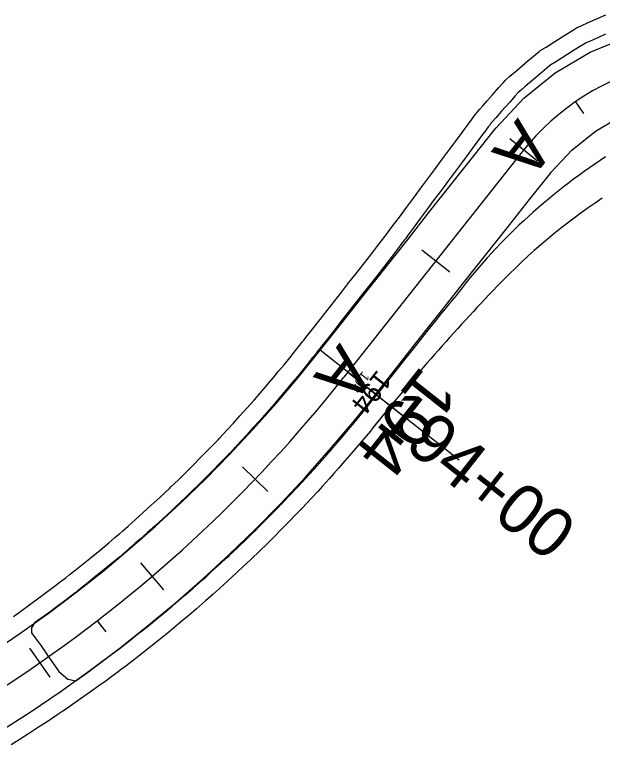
# Model space of a CAD drawing. Extents: x 1823824 to 1861612, y 706975 to 726130.
# Drawn here: x 1825898.7 to 1825981.6, y 712800.3 to 712904.6 of the extents above; entities that cross this region are included whole.
import ezdxf

# ---------------------------------------------------------------- set-up
doc = ezdxf.new("R2010")
doc.units = 0
for name, color, linetype in [('DR_X_Flood_Boundary', 7, 'Continuous'), ('GE_X_CL_10', 7, 'Continuous'), ('GE_X_CL_100', 7, 'Continuous'), ('GE_X_CL_20', 7, 'Continuous'), ('GE_X_CL_200', 7, 'Continuous'), ('GE_X_CL_50', 7, 'Continuous'), ('SC_Scratch2', 7, 'Continuous'), ('SC_Scratch5', 7, 'Continuous'), ('SC_Scratch6', 7, 'Continuous')]:
    doc.layers.add(name, color=color, linetype=linetype)

msp = doc.modelspace()

# ---------------------------------------------------------------- linework, layer by layer
at = {"layer": 'DR_X_Flood_Boundary'}
msp.add_line((1825970.3, 712885.19), (1825945.16, 712853.4), dxfattribs=at)
for centre, radius, start, end in [((1825997.75, 712863.48), 35, 65.2301, 141.6626), ((1825788.29, 712977.46), 200, 285.7144, 321.6626)]:
    msp.add_arc(centre, radius, start, end, dxfattribs=at)
at = {"layer": 'GE_X_CL_10'}
for p, q in [((1825977.85, 712892.27), (1825978.42, 712891.44)), ((1825945.73, 712854.12), (1825946.51, 712853.49)), ((1825910.32, 712819), (1825910.93, 712818.21))]:
    msp.add_line(p, q, dxfattribs=at)
at = {"layer": 'GE_X_CL_100'}
msp.add_line((1825945.73, 712854.12), (1825953.57, 712847.91), dxfattribs=at)
at = {"layer": 'GE_X_CL_20'}
for p, q in [((1825977.85, 712892.27), (1825978.99, 712890.62)), ((1825945.73, 712854.12), (1825947.3, 712852.87)), ((1825910.32, 712819), (1825911.54, 712817.42))]:
    msp.add_line(p, q, dxfattribs=at)
at = {"layer": 'GE_X_CL_200'}
msp.add_line((1825945.73, 712854.12), (1825961.42, 712841.71), dxfattribs=at)
at = {"layer": 'GE_X_CL_50'}
msp.add_line((1825945.73, 712854.12), (1825949.65, 712851.01), dxfattribs=at)
at = {"layer": 'SC_Scratch2'}
for p, q in [((1825980.69, 712888.15), (1825984.38, 712890.33)), ((1825977.35, 712885.47), (1825980.69, 712888.15)), ((1825974.43, 712882.34), (1825977.35, 712885.47)), ((1825974.22, 712882.08), (1825974.43, 712882.34)), ((1825971.36, 712878.47), (1825974.22, 712882.08)), ((1825968.26, 712874.54), (1825971.36, 712878.47)), ((1825965.16, 712870.62), (1825968.26, 712874.54)), ((1825962.06, 712866.7), (1825965.16, 712870.62)), ((1825958.96, 712862.78), (1825962.06, 712866.7)), ((1825955.85, 712858.86), (1825958.96, 712862.78)), ((1825952.75, 712854.94), (1825955.85, 712858.86)), ((1825949.65, 712851.01), (1825952.75, 712854.94)), ((1825949.09, 712850.3), (1825949.65, 712851.01)), ((1825946.45, 712847.04), (1825949.09, 712850.3)), ((1825943.14, 712843.13), (1825946.45, 712847.04)), ((1825939.74, 712839.3), (1825943.14, 712843.13)), ((1825936.24, 712835.55), (1825939.74, 712839.3)), ((1825932.64, 712831.9), (1825936.24, 712835.55)), ((1825928.96, 712828.34), (1825932.64, 712831.9)), ((1825925.19, 712824.87), (1825928.96, 712828.34)), ((1825921.33, 712821.49), (1825925.19, 712824.87)), ((1825917.39, 712818.22), (1825921.33, 712821.49)), ((1825913.37, 712815.04), (1825917.39, 712818.22)), ((1825909.27, 712811.96), (1825913.37, 712815.04)), ((1825905.09, 712808.99), (1825909.27, 712811.96)), ((1825900.85, 712806.12), (1825905.09, 712808.99)), ((1825896.53, 712803.36), (1825900.85, 712806.12))]:
    msp.add_line(p, q, dxfattribs=at)
for points in [[(1825929.56, 712846.92), (1825930.47, 712847.92), (1825931.46, 712849.02), (1825932.52, 712850.22), (1825933.32, 712851.14), (1825933.87, 712851.77), (1825934.17, 712852.12), (1825934.61, 712852.64), (1825935.2, 712853.35), (1825935.94, 712854.23), (1825936.7, 712855.15), (1825937.5, 712856.13), (1825938.32, 712857.16), (1825938.93, 712857.92), (1825939.33, 712858.42), (1825939.51, 712858.65), (1825939.98, 712859.25), (1825940.72, 712860.2), (1825941.75, 712861.51), (1825942.78, 712862.82), (1825943.81, 712864.13), (1825944.84, 712865.44), (1825945.87, 712866.75), (1825946.9, 712868.06), (1825947.93, 712869.37), (1825948.95, 712870.69), (1825949.97, 712872.01), (1825950.98, 712873.33), (1825951.99, 712874.66), (1825952.99, 712876), (1825953.98, 712877.34), (1825954.97, 712878.68), (1825955.96, 712880.02), (1825956.96, 712881.36), (1825957.95, 712882.7), (1825958.94, 712884.04), (1825959.93, 712885.38), (1825960.9, 712886.68), (1825961.84, 712887.96), (1825962.76, 712889.19), (1825963.4, 712890.06), (1825963.76, 712890.55), (1825963.86, 712890.67), (1825964.05, 712890.91), (1825964.35, 712891.25), (1825964.76, 712891.71), (1825965.33, 712892.37), (1825966.08, 712893.21), (1825966.99, 712894.24), (1825967.63, 712894.96), (1825967.98, 712895.35), (1825968.06, 712895.43), (1825968.61, 712895.9), (1825969.64, 712896.77), (1825971.14, 712898.05), (1825972.17, 712898.92), (1825972.73, 712899.39), (1825972.82, 712899.46), (1825972.91, 712899.52), (1825973.01, 712899.59), (1825973.11, 712899.65), (1825973.7, 712900.02), (1825974.78, 712900.7), (1825976.35, 712901.69), (1825977.43, 712902.36), (1825978.02, 712902.73), (1825978.12, 712902.78), (1825978.66, 712903.03), (1825979.64, 712903.47), (1825981.06, 712904.1), (1825982.14, 712904.58)], [(1825895.36, 712814.48), (1825899.4, 712817.21), (1825903.37, 712820.04), (1825907.27, 712822.96), (1825911.09, 712825.98), (1825914.84, 712829.1), (1825918.51, 712832.31), (1825922.1, 712835.61), (1825925.6, 712839), (1825929.02, 712842.48), (1825932.35, 712846.04), (1825935.59, 712849.68), (1825938.74, 712853.4), (1825941.24, 712856.5), (1825941.81, 712857.22), (1825944.91, 712861.14), (1825948.01, 712865.06), (1825951.11, 712868.98), (1825954.21, 712872.9), (1825957.31, 712876.83), (1825960.42, 712880.75), (1825963.52, 712884.67), (1825966.38, 712888.29), (1825966.66, 712888.63), (1825970.55, 712892.8), (1825975.01, 712896.38), (1825979.92, 712899.28), (1825985.2, 712901.46)], [(1825982.1, 712901.83), (1825981.1, 712901.38), (1825980.34, 712901.04), (1825979.82, 712900.81), (1825979.46, 712900.65), (1825979.26, 712900.56), (1825979.23, 712900.54), (1825978.67, 712900.19), (1825977.59, 712899.52), (1825976, 712898.51), (1825974.92, 712897.84), (1825974.36, 712897.49), (1825974.33, 712897.46), (1825974.3, 712897.44), (1825974.27, 712897.42), (1825974.24, 712897.4), (1825973.88, 712897.1), (1825973.2, 712896.53), (1825972.2, 712895.68), (1825971.38, 712894.98), (1825970.73, 712894.43), (1825970.27, 712894.03), (1825969.95, 712893.76), (1825969.78, 712893.62), (1825969.76, 712893.59), (1825969.35, 712893.14), (1825968.57, 712892.25), (1825967.41, 712890.94), (1825966.59, 712890.01), (1825966.13, 712889.49), (1825966.02, 712889.36), (1825965.93, 712889.27), (1825965.88, 712889.2), (1825965.85, 712889.17), (1825965.81, 712889.11), (1825965.76, 712889.05), (1825965.7, 712888.96), (1825965.57, 712888.79), (1825965.38, 712888.54), (1825965.13, 712888.2), (1825964.74, 712887.67), (1825964.21, 712886.96), (1825963.55, 712886.06), (1825962.78, 712885.02), (1825961.89, 712883.83), (1825960.9, 712882.49), (1825959.91, 712881.15), (1825958.92, 712879.81), (1825957.92, 712878.47), (1825956.93, 712877.13), (1825955.94, 712875.79), (1825954.95, 712874.45), (1825954.25, 712873.5), (1825953.84, 712872.95), (1825953.72, 712872.8), (1825953.34, 712872.31), (1825952.71, 712871.47), (1825951.81, 712870.3), (1825950.88, 712869.09), (1825949.89, 712867.82), (1825948.86, 712866.51)], [(1825948.86, 712866.51), (1825947.83, 712865.2), (1825946.8, 712863.89), (1825945.77, 712862.58), (1825944.74, 712861.27), (1825943.71, 712859.96), (1825942.69, 712858.65), (1825942, 712857.77), (1825941.64, 712857.32), (1825941.63, 712857.3), (1825941.56, 712857.22), (1825941.44, 712857.06), (1825941.27, 712856.84), (1825941.13, 712856.67), (1825941.04, 712856.55), (1825940.98, 712856.48), (1825940.68, 712856.11), (1825940.15, 712855.44), (1825939.38, 712854.48), (1825938.63, 712853.56), (1825937.9, 712852.68), (1825937.2, 712851.85), (1825936.72, 712851.27), (1825936.46, 712850.96), (1825936.41, 712850.91), (1825936.38, 712850.86), (1825936.35, 712850.83), (1825936.33, 712850.81), (1825936.22, 712850.68), (1825936.03, 712850.45), (1825935.75, 712850.12), (1825935.54, 712849.87), (1825935.4, 712849.71), (1825935.34, 712849.64), (1825934.96, 712849.21), (1825934.27, 712848.42), (1825933.26, 712847.28), (1825932.31, 712846.23), (1825931.44, 712845.27), (1825930.64, 712844.4), (1825930.09, 712843.81), (1825929.79, 712843.49), (1825929.75, 712843.45), (1825929.72, 712843.41), (1825929.69, 712843.39), (1825929.68, 712843.38), (1825929.59, 712843.28), (1825929.42, 712843.1), (1825929.17, 712842.83), (1825928.99, 712842.63), (1825928.87, 712842.51), (1825928.82, 712842.45), (1825928.42, 712842.05), (1825927.68, 712841.29), (1825926.6, 712840.18), (1825925.58, 712839.15), (1825924.61, 712838.19), (1825923.69, 712837.3), (1825923.07, 712836.69), (1825922.74, 712836.37), (1825922.71, 712836.34), (1825922.68, 712836.31), (1825922.67, 712836.3), (1825922.66, 712836.29), (1825922.58, 712836.22), (1825922.44, 712836.08), (1825922.24, 712835.88), (1825922.09, 712835.73), (1825921.99, 712835.64), (1825921.95, 712835.6), (1825921.53, 712835.22), (1825920.75, 712834.5), (1825919.61, 712833.43), (1825918.5, 712832.42), (1825917.43, 712831.46), (1825916.4, 712830.55), (1825915.7, 712829.94), (1825915.33, 712829.62), (1825915.3, 712829.59), (1825915.23, 712829.53), (1825915.12, 712829.43), (1825914.96, 712829.29), (1825914.84, 712829.19), (1825914.77, 712829.12), (1825914.74, 712829.1), (1825914.31, 712828.74), (1825913.49, 712828.05), (1825912.28, 712827.04), (1825911.08, 712826.05), (1825909.91, 712825.1), (1825908.75, 712824.18), (1825907.98, 712823.56), (1825907.59, 712823.25), (1825907.57, 712823.24), (1825907.53, 712823.2), (1825907.46, 712823.15), (1825907.35, 712823.06), (1825907.28, 712823.01), (1825907.24, 712822.97), (1825907.22, 712822.96), (1825906.79, 712822.63)], [(1825909.26, 712811.94), (1825909.27, 712811.95), (1825909.73, 712812.29), (1825910.64, 712812.97), (1825912, 712813.99), (1825912.91, 712814.67), (1825913.37, 712815.01), (1825913.38, 712815.01), (1825913.82, 712815.36), (1825914.71, 712816.05), (1825916.03, 712817.09), (1825916.91, 712817.79), (1825917.37, 712818.14), (1825917.39, 712818.16), (1825917.84, 712818.53), (1825918.72, 712819.26), (1825920.02, 712820.33), (1825920.9, 712821.05), (1825921.34, 712821.42), (1825921.36, 712821.43), (1825921.78, 712821.8), (1825922.62, 712822.53), (1825923.87, 712823.62), (1825924.72, 712824.36), (1825925.16, 712824.74), (1825925.2, 712824.78), (1825925.64, 712825.18), (1825926.48, 712825.94), (1825927.71, 712827.07), (1825928.55, 712827.83), (1825928.98, 712828.22), (1825929, 712828.25), (1825929.41, 712828.64), (1825930.2, 712829.4), (1825931.38, 712830.54), (1825932.19, 712831.31), (1825932.62, 712831.72), (1825932.67, 712831.77), (1825933.09, 712832.2), (1825933.89, 712833), (1825935.06, 712834.18), (1825935.85, 712834.98), (1825936.26, 712835.4), (1825936.29, 712835.43), (1825936.69, 712835.85), (1825937.44, 712836.64), (1825938.54, 712837.82), (1825939.3, 712838.63), (1825939.72, 712839.07), (1825939.78, 712839.13), (1825940.19, 712839.59), (1825940.94, 712840.43), (1825942.04, 712841.65), (1825942.78, 712842.48), (1825943.18, 712842.93), (1825943.22, 712842.97), (1825943.6, 712843.41), (1825944.3, 712844.24), (1825945.33, 712845.45), (1825946.05, 712846.29), (1825946.44, 712846.76), (1825946.52, 712846.84), (1825946.85, 712847.25), (1825947.43, 712847.97), (1825948.28, 712849.01), (1825948.85, 712849.71), (1825949.16, 712850.09), (1825949.2, 712850.14), (1825949.29, 712850.25), (1825949.42, 712850.42), (1825949.61, 712850.66), (1825950.09, 712851.25), (1825950.84, 712852.2), (1825951.88, 712853.5), (1825952.92, 712854.81), (1825953.96, 712856.11), (1825954.99, 712857.41), (1825956.03, 712858.72), (1825957.07, 712860.02), (1825958.11, 712861.33), (1825958.91, 712862.33), (1825959.48, 712863.04), (1825959.82, 712863.46), (1825960.29, 712864.02), (1825960.73, 712864.56)], [(1825950.97, 712848.36), (1825950.67, 712847.98), (1825950.14, 712847.33), (1825949.67, 712846.75), (1825949.25, 712846.24), (1825948.89, 712845.8), (1825948.28, 712845.07)], [(1825898.48, 712819.62), (1825899.34, 712820.24), (1825900.61, 712821.15), (1825901.89, 712822.08), (1825903.17, 712823.03), (1825904.45, 712824), (1825905.33, 712824.67), (1825905.82, 712825.04), (1825905.92, 712825.12), (1825906.37, 712825.47), (1825907.17, 712826.11), (1825908.33, 712827.04), (1825909.51, 712828), (1825910.72, 712828.99), (1825911.95, 712830.02), (1825912.82, 712830.75), (1825913.33, 712831.19), (1825913.49, 712831.32), (1825913.94, 712831.72), (1825914.69, 712832.38), (1825915.74, 712833.3), (1825916.83, 712834.28), (1825917.96, 712835.32), (1825919.14, 712836.41), (1825919.99, 712837.2), (1825920.52, 712837.7), (1825920.73, 712837.9), (1825921.18, 712838.34), (1825921.88, 712839.02), (1825922.82, 712839.94), (1825923.82, 712840.93), (1825924.88, 712842), (1825926, 712843.15), (1825926.83, 712844), (1825927.38, 712844.57), (1825927.63, 712844.84), (1825928.08, 712845.32), (1825928.72, 712846.01), (1825929.56, 712846.92)], [(1825948.28, 712845.07), (1825947.41, 712844.04), (1825946.29, 712842.72), (1825945.31, 712841.58), (1825944.46, 712840.6), (1825943.74, 712839.8), (1825943.11, 712839.1), (1825942.58, 712838.51), (1825942.15, 712838.03), (1825941.46, 712837.28), (1825940.53, 712836.28), (1825939.34, 712835.02), (1825938.32, 712833.94), (1825937.45, 712833.05), (1825936.76, 712832.34), (1825936.12, 712831.7), (1825935.54, 712831.11), (1825935.02, 712830.59), (1825934.26, 712829.84), (1825933.26, 712828.87), (1825932.01, 712827.67), (1825930.95, 712826.67), (1825930.09, 712825.86), (1825929.42, 712825.24), (1825928.77, 712824.65), (1825928.14, 712824.07), (1825927.54, 712823.52), (1825926.7, 712822.78), (1825925.63, 712821.83), (1825924.32, 712820.7), (1825923.24, 712819.77), (1825922.38, 712819.04), (1825921.74, 712818.51), (1825921.08, 712817.97), (1825920.41, 712817.41), (1825919.71, 712816.83), (1825918.8, 712816.09), (1825917.66, 712815.19), (1825916.3, 712814.12), (1825915.19, 712813.26), (1825914.34, 712812.61), (1825913.74, 712812.16), (1825913.08, 712811.67), (1825912.36, 712811.13), (1825911.57, 712810.54), (1825910.57, 712809.82), (1825909.37, 712808.95), (1825907.95, 712807.96), (1825906.83, 712807.17), (1825905.99, 712806.59), (1825905.44, 712806.22), (1825904.78, 712805.78), (1825904.01, 712805.26), (1825903.12, 712804.66), (1825902.04, 712803.96), (1825900.77, 712803.14), (1825899.31, 712802.21), (1825898.18, 712801.5)], [(1825906.79, 712822.63), (1825905.93, 712821.98), (1825904.64, 712821.01), (1825903.47, 712820.14), (1825902.42, 712819.37), (1825901.47, 712818.69), (1825901.02, 712818.01), (1825901.05, 712817.31), (1825901.57, 712816.6), (1825902.38, 712815.45), (1825903.49, 712813.87), (1825904.89, 712811.86), (1825906.15, 712810.74), (1825907.28, 712810.54), (1825909.26, 712811.94)]]:
    msp.add_lwpolyline(points, dxfattribs=at)
for centre, radius, start, end in [((1826027.55, 712814.3), 83.62, 122.9121, 143.0455), ((1826030.82, 712804.95), 88.62, 123.7111, 136.2473), ((1826189.65, 712652.89), 308.51, 136.2473, 141.1038)]:
    msp.add_arc(centre, radius, start, end, dxfattribs=at)
at = {"layer": 'SC_Scratch5'}
for points in [[(1825972.49, 712883.92), (1825968.6, 712887.06)], [(1825960.1, 712868.25), (1825956.17, 712871.35)], [(1825949.65, 712851.01), (1825941.81, 712857.22)], [(1825934.43, 712837.28), (1825930.82, 712840.75)], [(1825919.71, 712823.39), (1825916.46, 712827.2)], [(1825903.67, 712811.04), (1825900.82, 712815.15)]]:
    msp.add_lwpolyline(points, dxfattribs=at)

# ---------------------------------------------------------------- texts
at = {"layer": 'GE_X_CL_10'}
msp.add_text('194', height=1.4, rotation=231.6626, dxfattribs=at).set_placement((1825947.82, 712854.33))
at = {"layer": 'GE_X_CL_20'}
msp.add_text('194', height=2.8, rotation=231.6626, dxfattribs=at).set_placement((1825949.9, 712854.55))
at = {"layer": 'GE_X_CL_50'}
msp.add_text('194', height=7, rotation=231.6626, dxfattribs=at).set_placement((1825956.16, 712855.21))
at = {"layer": 'SC_Scratch5'}
msp.add_text('194+00', height=7, rotation=321.6626, dxfattribs=at).set_placement((1825949.44, 712846.72))
at = {"layer": 'SC_Scratch6'}
for p in [(1825969.73, 712890.1), (1825944.59, 712858.32)]:
    msp.add_text('A', height=7, rotation=231.6626, dxfattribs=at).set_placement(p)

doc.saveas('drawing.dxf')
